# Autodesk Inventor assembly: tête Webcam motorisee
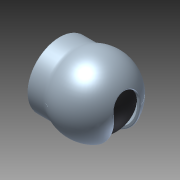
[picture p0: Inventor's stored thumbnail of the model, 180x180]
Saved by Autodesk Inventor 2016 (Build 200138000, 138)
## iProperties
Created: 2013-08
Part Number: tête Webcam motorisee
Document SubType Name: Assembly
Designer: hilarion
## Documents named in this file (3)
- S:\TSTI2D\Documents en consultation\etude de cas 1  webcam\Webcam motorisee\tête Webcam motorisee.iam
- S:\TSTI2D\Documents en consultation\etude de cas 1  webcam\Webcam motorisee\SE-Camera.iam
- S:\TSTI2D\Documents en consultation\etude de cas 1  webcam\Webcam motorisee\SE-Coques.iam
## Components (2 placed, 2 different names)
1. SE-Camera:1 [sub-assembly]
2. SE-Coques:1 [sub-assembly]
